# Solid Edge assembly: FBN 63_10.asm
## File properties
Title: Zylinder
Author: bmolnar
Template: iso assembly.asm
Last saved by: bmolnar
Revision: 10
Application: Solid Edge
Username: bmolnar
Dokumentum tartalom típus: 1
Document Number: FBN 63/10
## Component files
Kit.par
Profilrohr.par
Kolbenstange.par
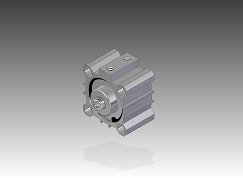
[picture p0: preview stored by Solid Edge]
